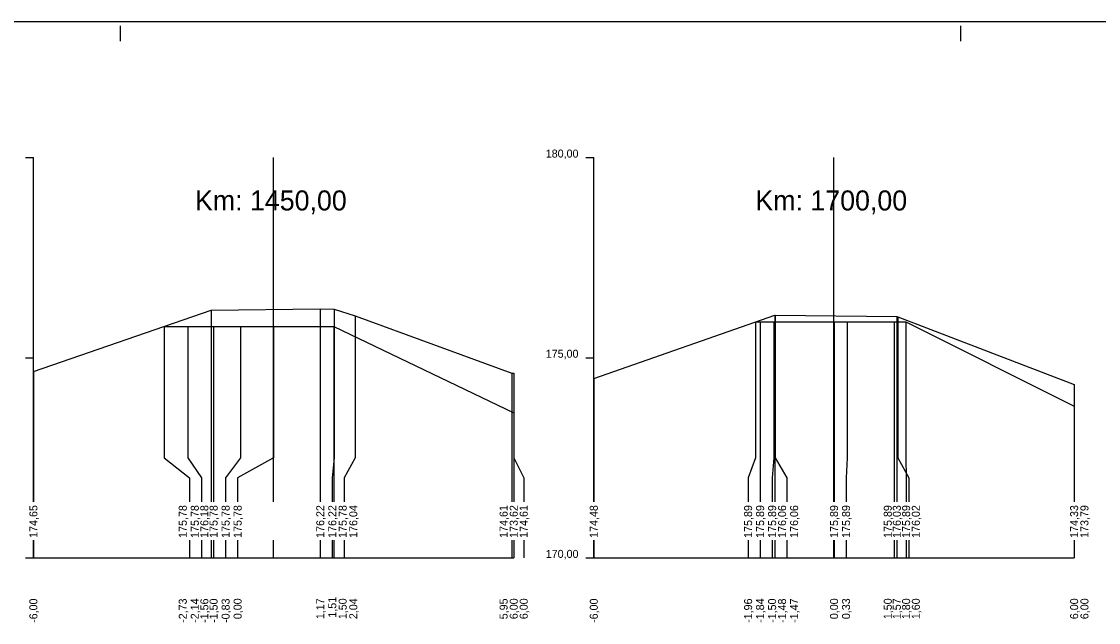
# Model space of a CAD drawing. Extents: x -614174 to -599765, y -1185887 to -1181080.
# Drawn here: x -608698 to -608671.1, y -1184468.3 to -1184453.29 of the extents above; entities that cross this region are included whole.
import ezdxf

# ---------------------------------------------------------------- set-up
doc = ezdxf.new("R2010")
doc.units = 0
for name, color, linetype in [('11', 7, 'Continuous'), ('16', 7, 'Continuous'), ('21', 7, 'Continuous'), ('28', 7, 'Continuous'), ('59', 7, 'Continuous'), ('8', 7, 'Continuous'), ('návrh', 7, 'Continuous')]:
    doc.layers.add(name, color=color, linetype=linetype)

msp = doc.modelspace()

# ---------------------------------------------------------------- linework, layer by layer
for points in [[(-608697.705, -1184462.037), (-608693.265, -1184460.505), (-608690.538, -1184460.47), (-608690.193, -1184460.474), (-608689.667, -1184460.646), (-608685.756, -1184462.076), (-608685.705, -1184462.076)], [(-608683.705, -1184462.206), (-608679.182, -1184460.629), (-608679.171, -1184460.629), (-608676.135, -1184460.659), (-608676.109, -1184460.667), (-608671.705, -1184462.355)], [(-608694.435, -1184460.908), (-608693.843, -1184460.908), (-608693.203, -1184460.908), (-608692.53, -1184460.908), (-608691.703, -1184460.908), (-608690.203, -1184460.908), (-608685.705, -1184463.066)], [(-608693.203, -1184460.908), (-608693.203, -1184460.908), (-608693.203, -1184460.908)], [(-608691.703, -1184460.908), (-608691.703, -1184460.908), (-608691.703, -1184460.908)], [(-608690.203, -1184460.908), (-608690.203, -1184460.908), (-608690.203, -1184460.908)], [(-608679.662, -1184460.796), (-608679.55, -1184460.796), (-608679.203, -1184460.796), (-608677.703, -1184460.796), (-608677.374, -1184460.796), (-608676.203, -1184460.796), (-608675.909, -1184460.796), (-608671.705, -1184462.896)], [(-608679.203, -1184460.796), (-608679.203, -1184460.796), (-608679.203, -1184460.796)], [(-608677.703, -1184460.796), (-608677.703, -1184460.796), (-608677.703, -1184460.796)], [(-608676.203, -1184460.796), (-608676.203, -1184460.796), (-608676.203, -1184460.796)]]:
    msp.add_lwpolyline(points)
at = {"layer": '11'}
for points in [[(-608693.265, -1184460.505), (-608693.265, -1184464.189), (-608693.265, -1184464.689), (-608693.265, -1184465.291)], [(-608690.538, -1184460.47), (-608690.538, -1184464.189), (-608690.538, -1184464.689), (-608690.538, -1184465.291)], [(-608690.193, -1184460.474), (-608690.193, -1184464.189), (-608690.238, -1184464.689), (-608690.238, -1184465.291)], [(-608689.667, -1184460.646), (-608689.667, -1184464.189), (-608689.938, -1184464.689), (-608689.938, -1184465.291)], [(-608679.182, -1184460.629), (-608679.182, -1184464.189), (-608679.182, -1184464.689), (-608679.182, -1184465.291)], [(-608679.171, -1184460.629), (-608679.171, -1184464.189), (-608678.882, -1184464.689), (-608678.882, -1184465.291)], [(-608676.135, -1184460.659), (-608676.135, -1184464.189), (-608676.135, -1184464.689), (-608676.135, -1184465.291)], [(-608676.109, -1184460.667), (-608676.109, -1184464.189), (-608675.835, -1184464.689), (-608675.835, -1184465.291)], [(-608694.435, -1184460.908), (-608694.435, -1184464.189), (-608693.803, -1184464.689), (-608693.803, -1184465.291)], [(-608693.843, -1184460.908), (-608693.843, -1184464.189), (-608693.503, -1184464.689), (-608693.503, -1184465.291)], [(-608693.203, -1184460.908), (-608693.203, -1184464.189), (-608693.203, -1184464.689), (-608693.203, -1184465.291)], [(-608692.53, -1184460.908), (-608692.53, -1184464.189), (-608692.903, -1184464.689), (-608692.903, -1184465.291)], [(-608691.703, -1184460.908), (-608691.703, -1184464.189), (-608692.603, -1184464.689), (-608692.603, -1184465.291)], [(-608690.203, -1184460.908), (-608690.203, -1184464.189), (-608690.203, -1184464.689), (-608690.203, -1184465.291)], [(-608679.662, -1184460.796), (-608679.662, -1184464.189), (-608679.85, -1184464.689), (-608679.85, -1184465.291)], [(-608679.55, -1184460.796), (-608679.55, -1184464.189), (-608679.55, -1184464.689), (-608679.55, -1184465.291)], [(-608679.203, -1184460.796), (-608679.203, -1184464.189), (-608679.25, -1184464.689), (-608679.25, -1184465.291)], [(-608677.703, -1184460.796), (-608677.703, -1184464.189), (-608677.703, -1184464.689), (-608677.703, -1184465.291)], [(-608677.374, -1184460.796), (-608677.374, -1184464.189), (-608677.403, -1184464.689), (-608677.403, -1184465.291)], [(-608676.203, -1184460.796), (-608676.203, -1184464.189), (-608676.203, -1184464.689), (-608676.203, -1184465.291)], [(-608675.909, -1184460.796), (-608675.909, -1184464.189), (-608675.903, -1184464.689), (-608675.903, -1184465.291)], [(-608697.705, -1184462.037), (-608697.705, -1184464.189), (-608697.705, -1184464.689), (-608697.705, -1184465.291)], [(-608685.756, -1184462.076), (-608685.756, -1184464.189), (-608685.756, -1184464.689), (-608685.756, -1184465.291)], [(-608685.705, -1184462.076), (-608685.705, -1184464.189), (-608685.456, -1184464.689), (-608685.456, -1184465.291)], [(-608683.705, -1184462.206), (-608683.705, -1184464.189), (-608683.705, -1184464.689), (-608683.705, -1184465.291)], [(-608671.705, -1184462.355), (-608671.705, -1184464.189), (-608671.705, -1184464.689), (-608671.705, -1184465.291)], [(-608685.705, -1184463.066), (-608685.705, -1184464.189), (-608685.705, -1184464.689), (-608685.705, -1184465.291)], [(-608671.705, -1184462.896), (-608671.705, -1184464.189), (-608671.705, -1184464.689), (-608671.705, -1184465.291)], [(-608697.705, -1184466.249), (-608697.705, -1184466.689)], [(-608693.803, -1184466.249), (-608693.803, -1184466.689)], [(-608693.503, -1184466.249), (-608693.503, -1184466.689)], [(-608693.265, -1184466.249), (-608693.265, -1184466.689)], [(-608693.203, -1184466.249), (-608693.203, -1184466.689)], [(-608692.903, -1184466.249), (-608692.903, -1184466.689)], [(-608692.603, -1184466.249), (-608692.603, -1184466.689)], [(-608690.538, -1184466.249), (-608690.538, -1184466.689)], [(-608690.238, -1184466.249), (-608690.238, -1184466.689)], [(-608690.203, -1184466.249), (-608690.203, -1184466.689)], [(-608689.938, -1184466.249), (-608689.938, -1184466.689)], [(-608685.756, -1184466.249), (-608685.756, -1184466.689)], [(-608685.705, -1184466.249), (-608685.705, -1184466.689)], [(-608685.456, -1184466.249), (-608685.456, -1184466.689)], [(-608683.705, -1184466.249), (-608683.705, -1184466.689)], [(-608679.85, -1184466.249), (-608679.85, -1184466.689)], [(-608679.55, -1184466.249), (-608679.55, -1184466.689)], [(-608679.25, -1184466.249), (-608679.25, -1184466.689)], [(-608679.182, -1184466.249), (-608679.182, -1184466.689)], [(-608678.882, -1184466.249), (-608678.882, -1184466.689)], [(-608677.703, -1184466.249), (-608677.703, -1184466.689)], [(-608677.403, -1184466.249), (-608677.403, -1184466.689)], [(-608676.203, -1184466.249), (-608676.203, -1184466.689)], [(-608676.135, -1184466.249), (-608676.135, -1184466.689)], [(-608675.903, -1184466.249), (-608675.903, -1184466.689)], [(-608675.835, -1184466.249), (-608675.835, -1184466.689)], [(-608671.705, -1184466.249), (-608671.705, -1184466.689)], [(-608671.705, -1184466.249), (-608671.705, -1184466.689)]]:
    msp.add_lwpolyline(points, dxfattribs=at)
at = {"layer": '16'}
for p, q in [((-608697.705, -1184466.689), (-608685.705, -1184466.689)), ((-608683.705, -1184466.689), (-608671.705, -1184466.689))]:
    msp.add_line(p, q, dxfattribs=at)
at = {"layer": '21'}
for p, q in [((-608697.905, -1184456.689), (-608697.705, -1184456.689)), ((-608683.905, -1184456.689), (-608683.705, -1184456.689)), ((-608697.905, -1184461.689), (-608697.705, -1184461.689)), ((-608683.905, -1184461.689), (-608683.705, -1184461.689)), ((-608697.905, -1184466.689), (-608697.705, -1184466.689)), ((-608683.905, -1184466.689), (-608683.705, -1184466.689))]:
    msp.add_line(p, q, dxfattribs=at)
at = {"layer": '28'}
for p, q in [((-608691.705, -1184465.291), (-608691.705, -1184456.689)), ((-608677.705, -1184465.291), (-608677.705, -1184456.689)), ((-608691.705, -1184466.689), (-608691.705, -1184466.249)), ((-608677.705, -1184466.689), (-608677.705, -1184466.249))]:
    msp.add_line(p, q, dxfattribs=at)
at = {"layer": '8'}
for p, q in [((-608697.705, -1184465.291), (-608697.705, -1184456.689)), ((-608683.705, -1184465.291), (-608683.705, -1184456.689)), ((-608697.705, -1184466.689), (-608697.705, -1184466.249)), ((-608683.705, -1184466.689), (-608683.705, -1184466.249))]:
    msp.add_line(p, q, dxfattribs=at)
at = {"layer": 'návrh'}
for p, q in [((-608716.532, -1184453.291), (-608632.532, -1184453.291)), ((-608695.532, -1184453.783), (-608695.532, -1184453.402)), ((-608674.532, -1184453.783), (-608674.532, -1184453.402))]:
    msp.add_line(p, q, dxfattribs=at)

# ---------------------------------------------------------------- texts
for p in [(-608694.435, -1184460.909), (-608679.662, -1184460.797)]:
    msp.add_text('+', height=0.001).set_placement(p)
at = {"layer": '16'}
for s, p in [('174,65', (-608697.605, -1184466.189)), ('175,78', (-608693.873, -1184466.189)), ('175,78', (-608693.573, -1184466.189)), ('176,18', (-608693.334, -1184466.189)), ('175,78', (-608693.103, -1184466.189)), ('175,78', (-608692.803, -1184466.189)), ('175,78', (-608692.503, -1184466.189)), ('176,22', (-608690.438, -1184466.189)), ('176,22', (-608690.138, -1184466.189)), ('175,78', (-608689.878, -1184466.189)), ('176,04', (-608689.613, -1184466.189)), ('174,61', (-608685.858, -1184466.189)), ('173,62', (-608685.605, -1184466.189)), ('174,61', (-608685.356, -1184466.189)), ('174,48', (-608683.605, -1184466.189)), ('175,89', (-608679.75, -1184466.189)), ('175,89', (-608679.45, -1184466.189)), ('175,89', (-608679.15, -1184466.189)), ('176,06', (-608678.901, -1184466.189)), ('176,06', (-608678.601, -1184466.189)), ('175,89', (-608677.603, -1184466.189)), ('175,89', (-608677.303, -1184466.189)), ('175,89', (-608676.261, -1184466.189)), ('176,03', (-608676.035, -1184466.189)), ('175,89', (-608675.803, -1184466.189)), ('176,02', (-608675.56, -1184466.189)), ('174,33', (-608671.605, -1184466.189)), ('173,79', (-608671.348, -1184466.189))]:
    msp.add_text(s, height=0.2, rotation=90, dxfattribs=at).set_placement(p)
at = {"layer": '21'}
for s, p in [('180,00', (-608684.905, -1184456.689)), ('175,00', (-608684.905, -1184461.689)), ('170,00', (-608684.905, -1184466.689))]:
    msp.add_text(s, height=0.2, dxfattribs=at).set_placement(p)
at = {"layer": '28'}
for s, p in [('Km: 1450,00', (-608693.668, -1184458.01)), ('Km: 1700,00', (-608679.668, -1184458.01))]:
    msp.add_text(s, height=0.5, dxfattribs=at).set_placement(p)
at = {"layer": '59'}
for s, p in [('-6,00', (-608697.605, -1184468.313)), ('-2,73', (-608693.873, -1184468.313)), ('-2,14', (-608693.573, -1184468.312)), ('-1,56', (-608693.334, -1184468.313)), ('-1,50', (-608693.103, -1184468.313)), ('-0,83', (-608692.803, -1184468.313)), ('0,00', (-608692.503, -1184468.22)), ('1,17', (-608690.438, -1184468.22)), ('1,51', (-608690.138, -1184468.182)), ('1,50', (-608689.878, -1184468.22)), ('2,04', (-608689.613, -1184468.219)), ('5,95', (-608685.858, -1184468.222)), ('6,00', (-608685.605, -1184468.22)), ('6,00', (-608685.356, -1184468.22)), ('-6,00', (-608683.605, -1184468.313)), ('-1,96', (-608679.75, -1184468.313)), ('-1,84', (-608679.45, -1184468.312)), ('-1,50', (-608679.15, -1184468.313)), ('-1,48', (-608678.901, -1184468.314)), ('-1,47', (-608678.601, -1184468.313)), ('0,00', (-608677.603, -1184468.22)), ('0,33', (-608677.303, -1184468.22)), ('1,50', (-608676.261, -1184468.22)), ('1,57', (-608676.035, -1184468.22)), ('1,80', (-608675.803, -1184468.22)), ('1,60', (-608675.56, -1184468.22)), ('6,00', (-608671.605, -1184468.22)), ('6,00', (-608671.348, -1184468.22))]:
    msp.add_text(s, height=0.2, rotation=90, dxfattribs=at).set_placement(p)

doc.saveas('drawing.dxf')
